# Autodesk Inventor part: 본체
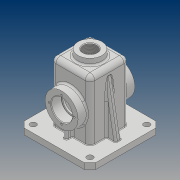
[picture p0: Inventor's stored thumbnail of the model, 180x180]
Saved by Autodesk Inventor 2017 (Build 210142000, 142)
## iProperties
Part Number: 본체
Material: 일반
Document SubType Name: Modeling
Designer: 20
Density: 1 g/cm^3
Appearance: 기본값
Mass: 292.705 g
Surface Area: 898.371 cm^2
Volume: 292.705 cm^3
Author: 20
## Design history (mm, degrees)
sketch "스케치1"
  geometry: L1 (-32.5, -32.5)-(32.5, -32.5); L2 (32.5, -32.5)-(32.5, 32.5); L3 (32.5, 32.5)-(-32.5, 32.5); L4 (-32.5, 32.5)-(-32.5, -32.5); L5 (-32.5, -32.5)-(32.5, 32.5); L6 (32.5, -32.5)-(-32.5, 32.5); 1 further point
  constraints: 12 end point, 2 midpoint, 2 parallel, 1 horizontal, 1 perpendicular
  dimensions: "d0" = 65 distance of L3.end L2.end; "d1" = 65 distance of L2.end L1.end
extrude "돌출1" new body sketch "스케치1" distance "d2" = 110; taper "d3" = 0 deg
fillet "모깎기1" dims "d4" = 8
feature "쉘1" dims "d5" = 5
node "작업 평면1"
sketch "스케치2"
  geometry: C1 r 20 at (0, 0); 1 further point
  constraints: 1 centre point, 1 coincident
  dimensions: "d7" = 40 diameter of C1
extrude "돌출2" join sketch "스케치2" stored distance "d8" = 110; taper "d9" = 5 deg
hole "구멍1" diameter "d12" = 22.835; stored, may be unused: countersink angle "d16" = 90 deg, drill point angle "d18" = 118 deg; dims "d10" = 10, "d11" = 10, "d13" = 50, "d14" = 4, "d15" = 2, "d17" = 59.3
node "작업 평면2"
sketch "스케치3"
  geometry: L1 (-27.5, -24.5)-(-27.5, 24.5) reference; L2 (24.5, -27.5)-(-24.5, -27.5) reference; L3 (27.5, 24.5)-(27.5, -24.5) reference; L4 (-24.5, 27.5)-(24.5, 27.5) reference; L5 (60, -60)-(-60, -60); L6 (-60, -60)-(-60, 60); L7 (-60, 60)-(60, 60); L8 (60, 60)-(60, -60); L9 (60, -60)-(-60, 60); L10 (-60, -60)-(60, 60); A1 r 3 centre (-24.5, -24.5) between (-27.5, -24.5) and (-24.5, -27.5) reference; A2 r 3 centre (24.5, -24.5) between (24.5, -27.5) and (27.5, -24.5) reference; A3 r 3 centre (24.5, 24.5) between (27.5, 24.5) and (24.5, 27.5) reference; A4 r 3 centre (-24.5, 24.5) between (-24.5, 27.5) and (-27.5, 24.5) reference; 1 further point
  constraints: 12 end point, 2 midpoint, 2 parallel, 1 horizontal, 1 perpendicular
  dimensions: "d20" = 120 distance of L6.end L7.end; "d21" = 120 distance of L5.end L6.end
extrude "돌출3" join sketch "스케치3" distance "d22" = 10; taper "d23" = 0 deg
sketch "스케치4"
  geometry: L1 (-60, 10)-(60, 10) reference; L2 (-48, 10)-(-42.625, 40.485); L3 (-60, 10)-(-60, 0) reference; 1 further point
  constraints: 2 end point, 1 point on line
  dimensions: "d24" = 10 deg angle of L3 L2; "d25" = 12 distance from line of L3 L2.start
feature "리브1" sketch "스케치4" dims "d26" = 1, "d27" = 10, "d28" = 0, "d29" = 0, "d30" = 1, "d31" = 1
node "작업 평면3"
sketch "스케치6"
  geometry: L1 (84.5, -102)-(-35.5, -102) reference; C1 r 27.5 at (24.5, -47); 2 further points
  constraints: 1 centre point, 1 midpoint, 1 vertical alignment
  dimensions: "d35" = 55 diameter of C1; "d36" = 55 distance from line of L1 C1.centre
extrude "돌출4" join sketch "스케치6" stored distance "d37" = 15; taper "d38" = 0 deg
sketch "스케치7"
  geometry: L1 (-47.5, 27.5)-(-47.5, 82.5) reference; L2 (-47.5, 55)-(41.269, 55); L3 (-47.5, 72.5)-(-30.5, 72.5); L4 (-30.5, 72.5)-(-30.5, 70); L5 (-30.5, 70)-(-27.5, 70); L6 (-27.5, 0)-(-27.5, 102) reference; L7 (-47.5, 72.5)-(-47.5, 55); L8 (-27.5, 70)-(-27.5, 55); 1 further point
  constraints: 12 end point, 3 horizontal, 3 point on line, 3 vertical, 1 midpoint
  dimensions: "d39" = 17 distance of L3.start L3.end; "d40" = 35 diameter of L3 L2; "d41" = 30 diameter of L5 L2
revolve "회전1" sketch "스케치7" stored, may be unused: angle "d42" = 90 deg
sketch "스케치8" dims "d43" = 42
  geometry: L1 (0, 0)-(0, 21); C1 r 17.5 at (0, 0) reference; 3 further points
  constraints: 2 coincident, 2 end point, 1 vertical, 1 vertical alignment, 2 other
hole "구멍2" sketch "스케치8" at (0, 21) diameter "d44" = 3.242; stored, may be unused: countersink angle "d48" = 90 deg, drill point angle "d50" = 118 deg; dims "d45" = 8, "d46" = 4, "d47" = 2, "d49" = 10
sketch "스케치9"
  geometry: L1 (60, 10)-(-60, 10) reference; L2 (-42.5, 10)-(-42.5, 23.769); L3 (-32.5, 10)-(-32.5, 42.51) reference; L4 (-27.5, 0)-(-27.5, 102) reference; 1 further point
  constraints: 2 end point, 1 point on line, 1 vertical
  dimensions: "d55" = 15 distance between parallel lines of L2 L4
feature "리브2" sketch "스케치9" dims "d56" = 1, "d57" = 6, "d58" = 0, "d59" = 0, "d60" = 1, "d61" = 1
sketch "스케치10"
  geometry: L1 (-60, 60)-(-60, -60) reference; L2 (60, 60)-(-60, 60) reference; C1 r 5 at (-47.5, 47.5); 1 further point
  constraints: 1 centre point
  dimensions: "d62" = 10 diameter of C1; "d63" = 12.5 distance from line of L1 C1.centre; "d64" = 12.5 distance from line of L2 C1.centre
extrude "돌출5" cut sketch "스케치10" distance "d65" = 10; taper "d66" = 0 deg
chamfer "모따기1" distance "d73" = 10; stored, may be unused: second distance "d74" = 2, angle "d75" = 45 deg
fillet "모깎기2" dims "d76" = 3
fillet "모깎기3" dims "d77" = 3
fillet "모깎기4" dims "d78" = 1
fillet "모깎기5" dims "d79" = 3
chamfer "모따기2" distance "d80" = 1; stored, may be unused: second distance "d81" = 2, angle "d82" = 45 deg
fillet "모깎기6" dims "d83" = 0.3
node "작업 평면4"
sketch "스케치11"
  geometry: L1 (57, 0)-(57, 91) reference; L2 (44.5, -18)-(4.5, -18) reference; 2 further points
  constraints: 1 other
  dimensions: "d85" = 32.5 distance from line of L1 point (24.5, 8); "d86" = 26 distance from line of point (24.5, 8) L2
feature "엠보싱1" sketch "스케치11" dims "d0" = 65, "d1" = 65, "d87" = 0.5, "d88" = 0
node "솔리드1"
mirror "미러1"
pattern_circular "원형 패턴1" dims angle "d52" = 360 deg
mirror "미러2"
pattern_linear "직사각형 패턴1" dims "d69" = 95, "d72" = -95
other parameters: "d34" = 15, "d84" = 72.75
